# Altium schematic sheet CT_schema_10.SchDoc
size 287 x 160 mm
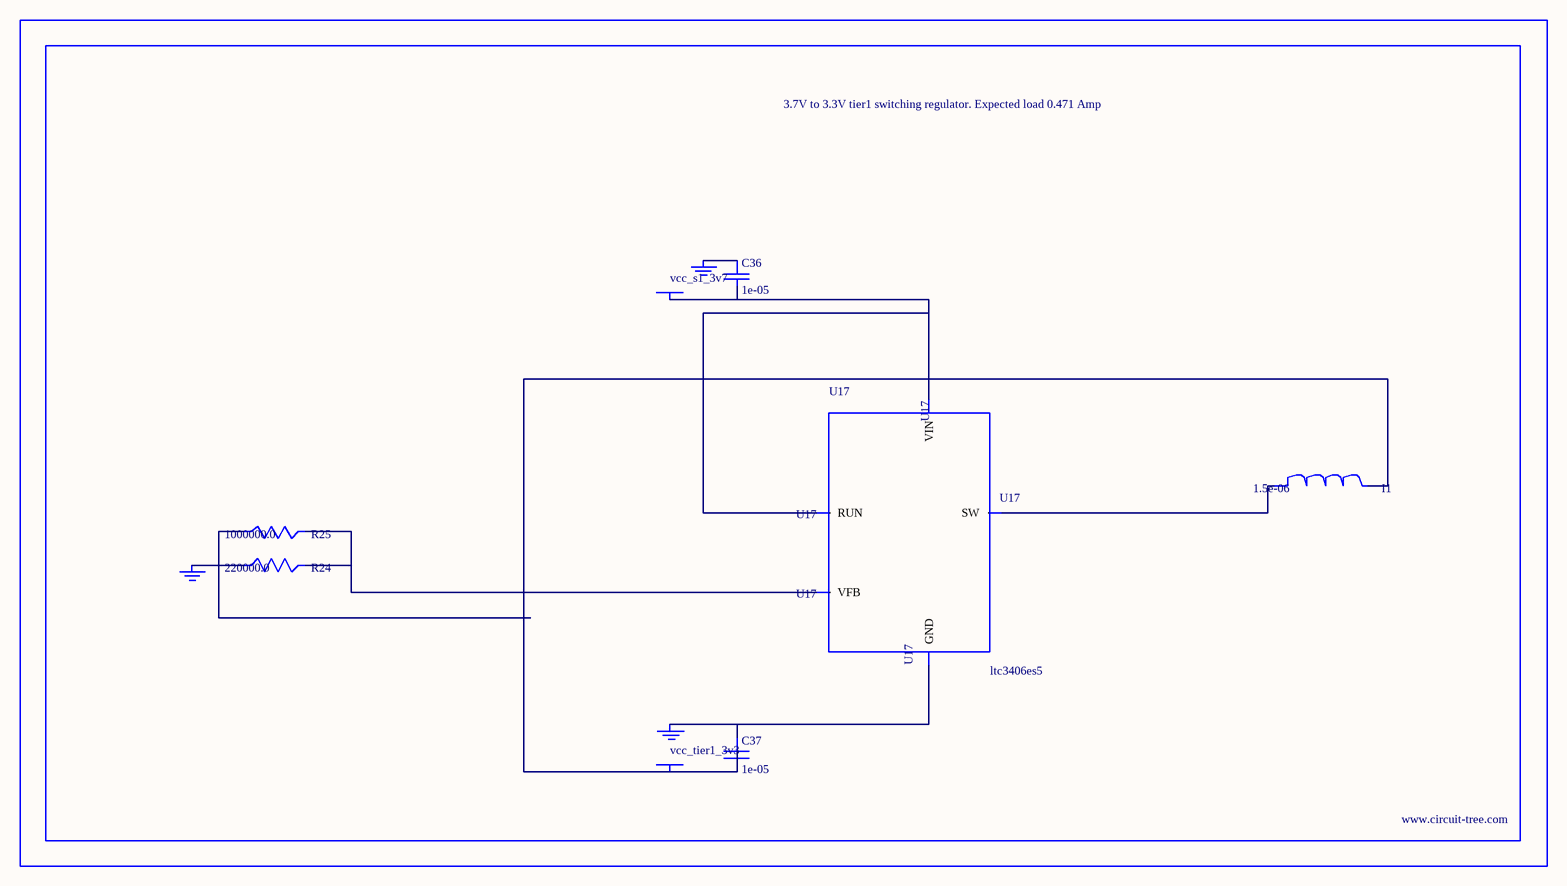
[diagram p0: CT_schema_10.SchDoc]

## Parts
BORDER9  (no value)
C36  1e-05  [C0805]
C37  1e-05  [C0805]
GND_INSTANCE_9_0  (no value)
GND_INSTANCE_9_1  (no value)
GND_INSTANCE_9_2  (no value)
I1  1.5e-06  [L0806]
POWER_INSTANCE_9_0  vcc_tier1_3v3
POWER_INSTANCE_9_1  vcc_s1_3v7
R24  220000.0  [R0603]
R25  1000000.0  [R0603]
U17  ltc3406es5  [TSOT-23-5]

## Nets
NetC36_1: C36.1 GND_INSTANCE_9_1.0(GND)
NetC36_2: C36.2 POWER_INSTANCE_9_1.0(PWR) U17.1(RUN) U17.4(VIN)
NetC37_1: C37.1 GND_INSTANCE_9_0.0(GND) U17.2(GND)
NetC37_2: C37.2 I1.2 POWER_INSTANCE_9_0.0(PWR) R25.1
NetGND_INSTANCE_9_2_0: GND_INSTANCE_9_2.0(GND) R24.1
NetI1_1: I1.1 U17.3(SW)
NetR24_2: R24.2 R25.2 U17.5(VFB)

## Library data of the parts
BORDER9 = BORDER_PAGE9
C36 C37 = C0805C106K8RACTU
GND_INSTANCE_9_0-GND_INSTANCE_9_2 = GND
I1 = L0806C1R5MDWIT
POWER_INSTANCE_9_0 POWER_INSTANCE_9_1 = PWR
R24 = RC0603JR-07220KL
R25 = RC0603JR-071ML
